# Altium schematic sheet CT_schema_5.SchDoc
size 517 x 390 mm
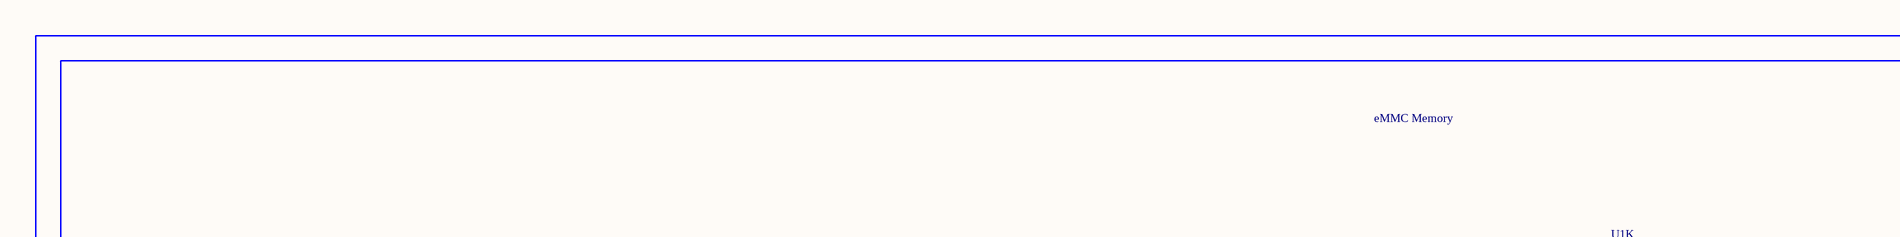
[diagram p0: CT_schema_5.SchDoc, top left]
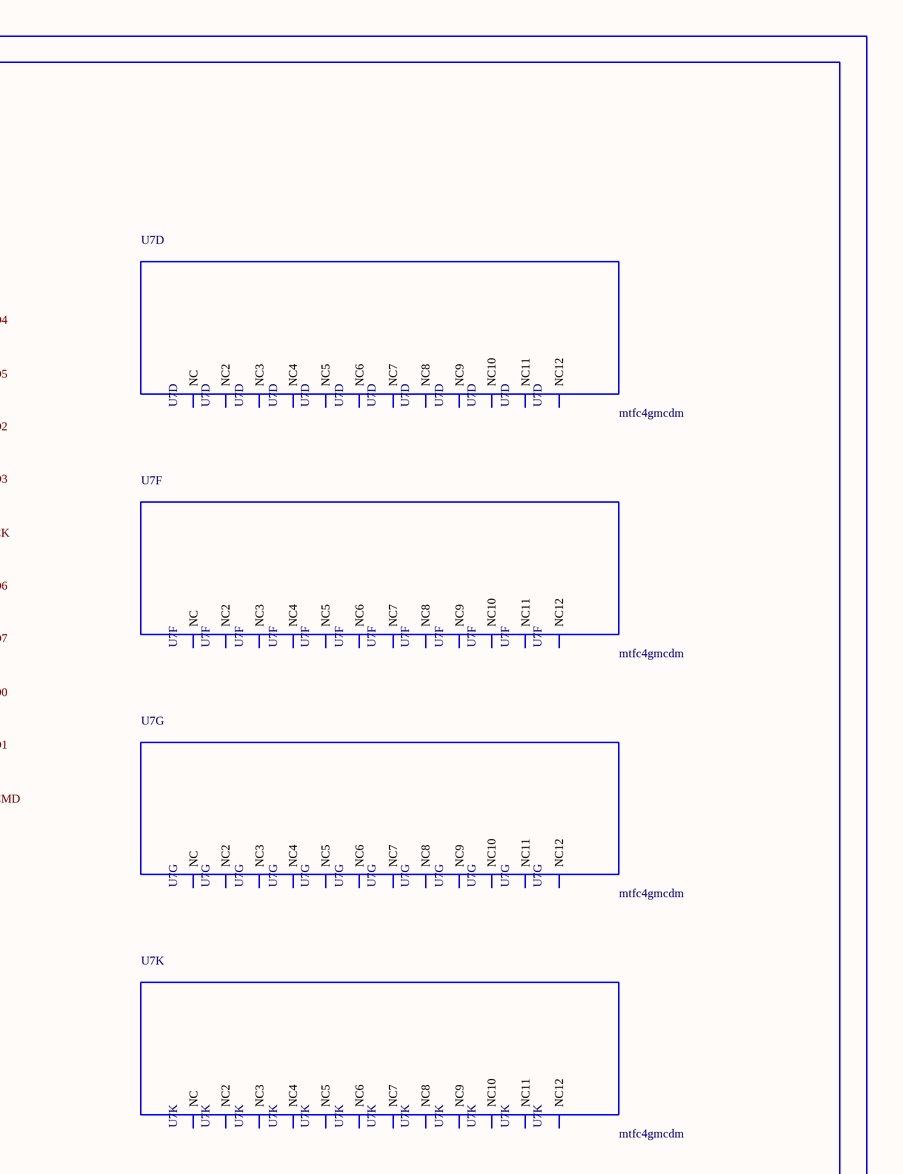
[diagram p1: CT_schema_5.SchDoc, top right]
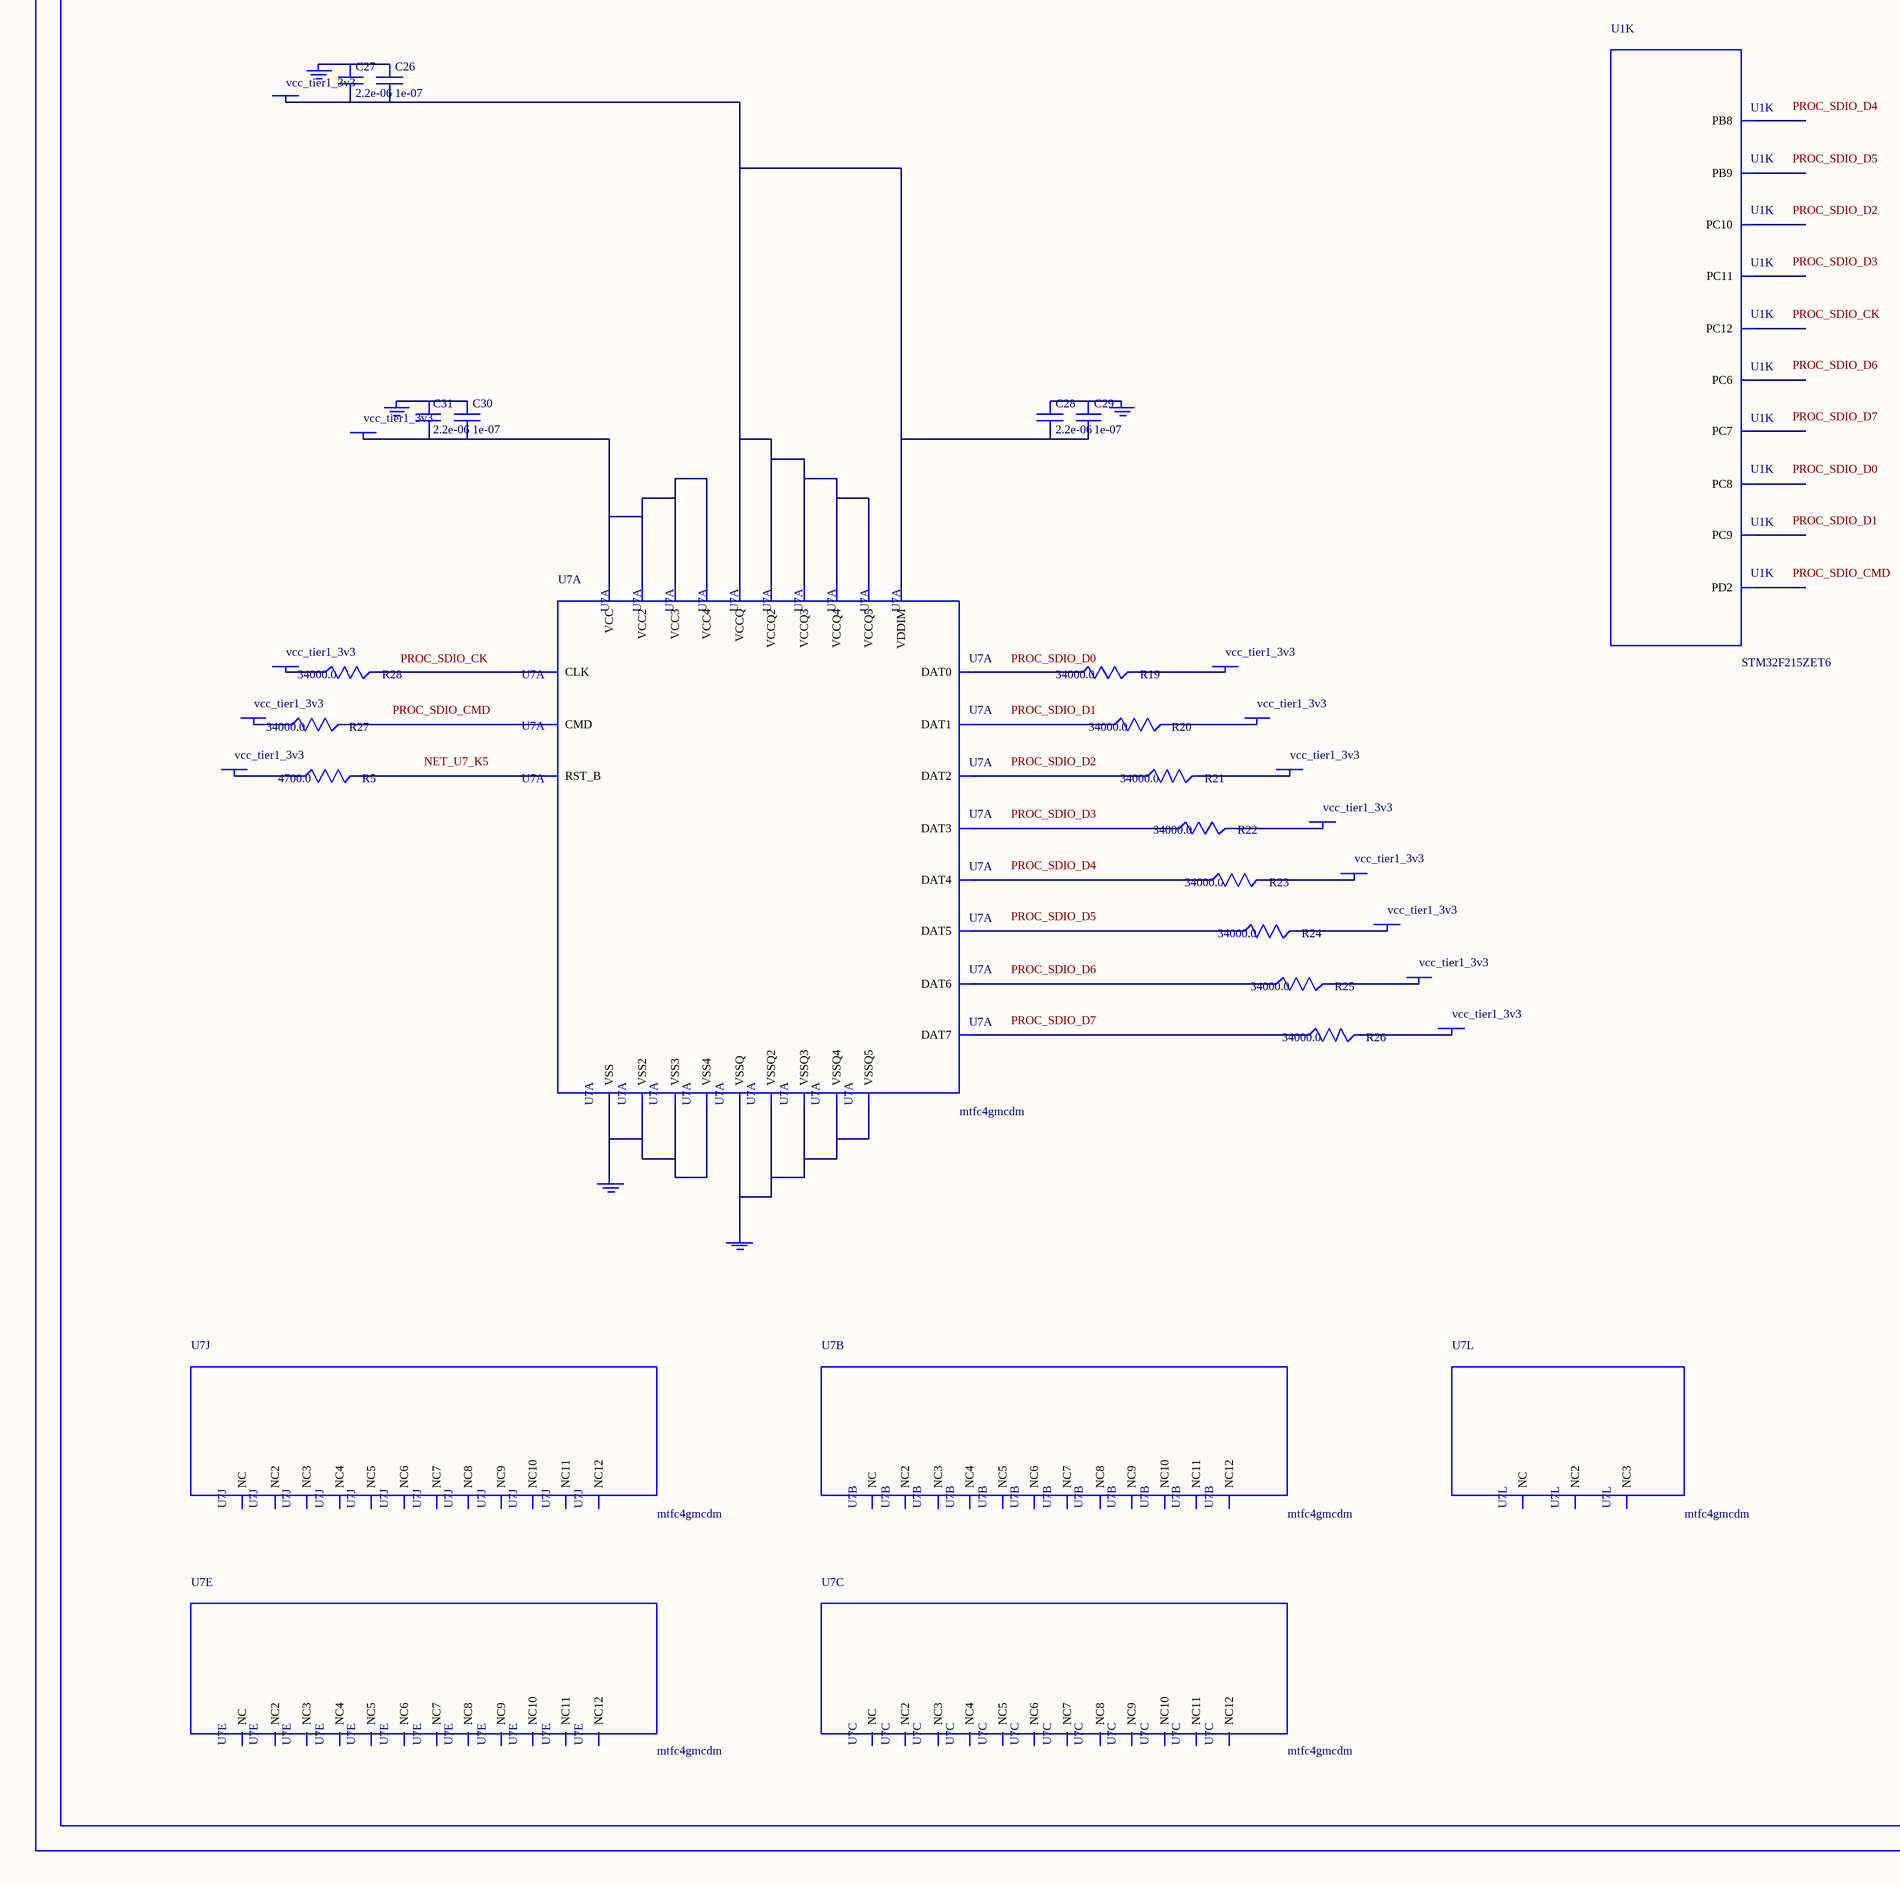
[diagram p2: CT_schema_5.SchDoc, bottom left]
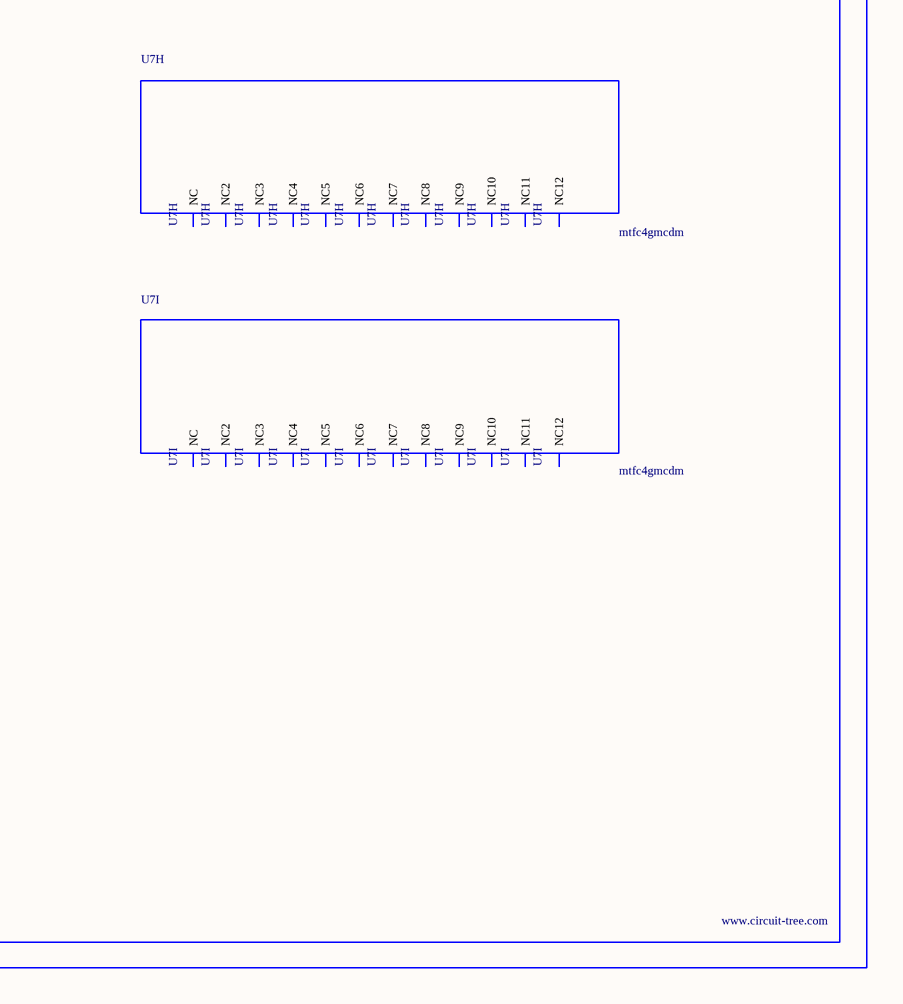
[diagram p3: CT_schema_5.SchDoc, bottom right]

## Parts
BORDER4  (no value)
C26  1e-07  [C0402]
C27  2.2e-06  [C0603]
C28  2.2e-06  [C0603]
C29  1e-07  [C0402]
C30  1e-07  [C0402]
C31  2.2e-06  [C0603]
GND_INSTANCE_4_0  (no value)
GND_INSTANCE_4_1  (no value)
GND_INSTANCE_4_2  (no value)
GND_INSTANCE_4_3  (no value)
GND_INSTANCE_4_4  (no value)
POWER_INSTANCE_4_0  vcc_tier1_3v3
POWER_INSTANCE_4_1  vcc_tier1_3v3
POWER_INSTANCE_4_2  vcc_tier1_3v3
POWER_INSTANCE_4_3  vcc_tier1_3v3
POWER_INSTANCE_4_4  vcc_tier1_3v3
POWER_INSTANCE_4_5  vcc_tier1_3v3
POWER_INSTANCE_4_6  vcc_tier1_3v3
POWER_INSTANCE_4_7  vcc_tier1_3v3
POWER_INSTANCE_4_8  vcc_tier1_3v3
POWER_INSTANCE_4_9  vcc_tier1_3v3
POWER_INSTANCE_4_10  vcc_tier1_3v3
POWER_INSTANCE_4_11  vcc_tier1_3v3
POWER_INSTANCE_4_12  vcc_tier1_3v3
R5  4700.0  [R0603]
R19  34000.0  [R0603]
R20  34000.0  [R0603]
R21  34000.0  [R0603]
R22  34000.0  [R0603]
R23  34000.0  [R0603]
R24  34000.0  [R0603]
R25  34000.0  [R0603]
R26  34000.0  [R0603]
R27  34000.0  [R0603]
R28  34000.0  [R0603]
U1  STM32F215ZET6  [LQFP144]  (part K of 12)
U7  mtfc4gmcdm  [TFBGA-153]  (parts A,B,C,D,E,F,G,H,I,J,K,L of 12)

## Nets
NetC26_1: C26.1 C27.1 GND_INSTANCE_4_0.0(GND)
NetC26_2: C26.2 C27.2 C28.2 C29.2 POWER_INSTANCE_4_0.0(PWR) U7.C2(VDDIM) U7.C6(VCCQ) U7.M4(VCCQ2) U7.N4(VCCQ3) U7.P3(VCCQ4) U7.P5(VCCQ5)
NetC28_1: C28.1 C29.1 GND_INSTANCE_4_1.0(GND)
NetC30_1: C30.1 C31.1 GND_INSTANCE_4_2.0(GND)
NetC30_2: C30.2 C31.2 POWER_INSTANCE_4_1.0(PWR) U7.E6(VCC) U7.F5(VCC2) U7.J10(VCC3) U7.K9(VCC4)
NetGND_INSTANCE_4_3_0: GND_INSTANCE_4_3.0(GND) U7.E7(VSS) U7.G5(VSS2) U7.H10(VSS3) U7.K8(VSS4)
NetGND_INSTANCE_4_4_0: GND_INSTANCE_4_4.0(GND) U7.C4(VSSQ) U7.N2(VSSQ2) U7.N5(VSSQ3) U7.P4(VSSQ4) U7.P6(VSSQ5)
NetPOWER_INSTANCE_4_2_0: POWER_INSTANCE_4_2.0(PWR) R19.2
NetPOWER_INSTANCE_4_3_0: POWER_INSTANCE_4_3.0(PWR) R20.2
NetPOWER_INSTANCE_4_4_0: POWER_INSTANCE_4_4.0(PWR) R21.2
NetPOWER_INSTANCE_4_5_0: POWER_INSTANCE_4_5.0(PWR) R22.2
NetPOWER_INSTANCE_4_6_0: POWER_INSTANCE_4_6.0(PWR) R23.2
NetPOWER_INSTANCE_4_7_0: POWER_INSTANCE_4_7.0(PWR) R24.2
NetPOWER_INSTANCE_4_8_0: POWER_INSTANCE_4_8.0(PWR) R25.2
NetPOWER_INSTANCE_4_9_0: POWER_INSTANCE_4_9.0(PWR) R26.2
NetPOWER_INSTANCE_4_10_0: POWER_INSTANCE_4_10.0(PWR) R27.1
NetPOWER_INSTANCE_4_11_0: POWER_INSTANCE_4_11.0(PWR) R28.1
NetPOWER_INSTANCE_4_12_0: POWER_INSTANCE_4_12.0(PWR) R5.1
NetR5_2: R5.2 U7.K5(RST_B)
NetR19_1: R19.1 U7.A3(DAT0)
NetR20_1: R20.1 U7.A4(DAT1)
NetR21_1: R21.1 U7.A5(DAT2)
NetR22_1: R22.1 U7.B2(DAT3)
NetR23_1: R23.1 U7.B3(DAT4)
NetR24_1: R24.1 U7.B4(DAT5)
NetR25_1: R25.1 U7.B5(DAT6)
NetR26_1: R26.1 U7.B6(DAT7)
NetR27_2: R27.2 U7.M5(CMD)
NetR28_2: R28.2 U7.M6(CLK)

Not connected (* = marked no-connect by the designer): U1 96(PC6) 97(PC7) 98(PC8) 99(PC9) 111(PC10) 112(PC11) 113(PC12) 116(PD2) 139(PB8) 140(PB9); U7 A1(NC) A2(NC7) A6(NC8) A7(NC9) A8(NC10) A9(NC11) A10(NC2) A11(NC3) A12(NC4) A13(NC5) A14(NC6) B1(NC12) B7(NC6) B8(NC7) B9(NC8) B10(NC) B11(NC2) B12(NC3) B13(NC4) B14(NC5) C1(NC9) C3(NC10) C5(NC11) C7(NC12) C8(NC6) C9(NC7) C10(NC) C11(NC2) C12(NC3) C13(NC4) C14(NC5) D1(NC8) D2(NC10) D3(NC11) D4(NC12) D12(NC9) D13(NC) D14(NC2) E1(NC3) E2(NC8) E3(NC9) E5(NC10) E8(NC11) E9(NC12) E10(NC4) E12(NC5) E13(NC6) E14(NC7) F1(NC) F2(NC6) F3(NC7) F10(NC2) F12(NC3) F13(NC4) F14(NC5) G1(NC8) G2(NC11) G3(NC12) G10(NC9) G12(NC10) G13(NC) G14(NC2) H1(NC3) H2(NC7) H3(NC8) H5(NC9) H12(NC4) H13(NC5) H14(NC6) J1(NC10) J2(NC11) J3(NC12) J5(NC4) J12(NC) J13(NC2) J14(NC3) K1(NC5) K2(NC9) K3(NC10) K6(NC11) K7(NC12) K10(NC6) K12(NC7) K13(NC8) K14(NC) L1(NC2) L2(NC6) L3(NC7) L12(NC3) L13(NC4) L14(NC5) M1(NC8) M2(NC9) M3(NC10) M7(NC11) M8(NC12) M9(NC6) M10(NC) M11(NC2) M12(NC3) M13(NC4) M14(NC5) N1(NC7) N3(NC8) N6(NC9) N7(NC10) N8(NC11) N9(NC12) N10(NC) N11(NC2) N12(NC3) N13(NC4) N14(NC5) P1(NC6) P2(NC9) P7(NC10) P8(NC11) P9(NC12) P10(NC7) P11(NC8) P12(NC) P13(NC2) P14(NC3)

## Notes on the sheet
- Labels drawn without touching a wire or pin: NET_U7_K5, PROC_SDIO_CK, PROC_SDIO_CMD, PROC_SDIO_D0, PROC_SDIO_D1, PROC_SDIO_D2, PROC_SDIO_D3, PROC_SDIO_D4, PROC_SDIO_D5, PROC_SDIO_D6, PROC_SDIO_D7

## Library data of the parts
BORDER4 = BORDER_PAGE4
C26 C29 C30 = C0402C104K3RACTU
C27 C28 C31 = C0603C225K8RACTU
GND_INSTANCE_4_0-GND_INSTANCE_4_4 = GND
POWER_INSTANCE_4_0-POWER_INSTANCE_4_12 = PWR
R5 = RC0603JR-074K7L
R19-R28 = ERA3ARB3402V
